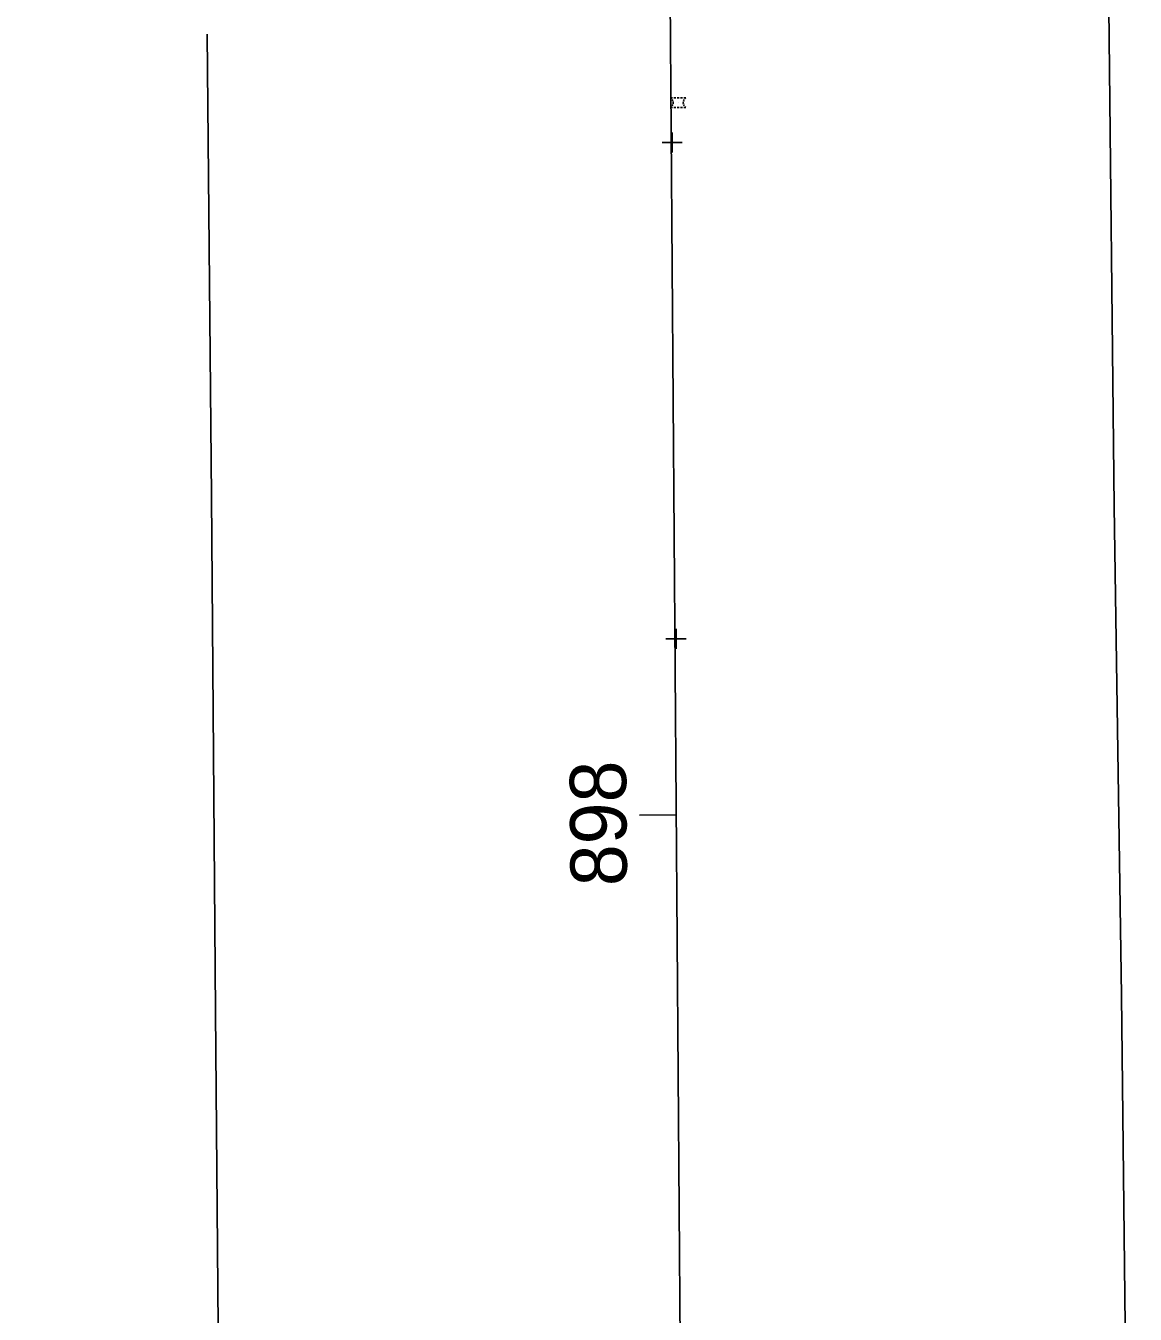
# Model space of a CAD drawing. Extents: x 1546689 to 1550004, y 741079 to 745265.
# Drawn here: x 1548796.6 to 1548851.8, y 745044.7 to 745108.8 of the extents above; entities that cross this region are included whole.
import ezdxf

# ---------------------------------------------------------------- set-up
doc = ezdxf.new("R2010")
doc.units = 0
for name, color, linetype in [('BR_P_Brg_Pad_Hidden', 7, 'Continuous'), ('BR_P_Det_Hidden', 7, 'Continuous'), ('BR_P_Drain_Hidden', 7, 'Continuous'), ('BR_P_Gen_Waterproofing', 7, 'Continuous'), ('BR_P_Slab_Const_Joint', 7, 'Continuous')]:
    doc.layers.add(name, color=color, linetype=linetype)

msp = doc.modelspace()

# ---------------------------------------------------------------- linework, layer by layer
at = {"layer": 'BR_P_Brg_Pad_Hidden'}
msp.add_lwpolyline([(1548851.762, 744992.557), (1548851.612, 745010.399), (1548851.363, 745035.194), (1548851.082, 745060.569), (1548850.709, 745084.888), (1548850.438, 745111.263), (1548850.35, 745126.508)], dxfattribs=at)
at = {"layer": 'BR_P_Det_Hidden'}
for p, q in [((1548827.57, 745248.795), (1548832.816, 744559.562)), ((1548827.109, 745069.54), (1548828.934, 745069.553))]:
    msp.add_line(p, q, dxfattribs=at)
at = {"layer": 'BR_P_Drain_Hidden'}
msp.add_lwpolyline([(1548796.58, 745026.104), (1548800.826, 745026.412), (1548804.475, 745028.932), (1548806.243, 745034.133), (1548806.211, 745036.245), (1548806.019, 745059.777), (1548805.812, 745085.387), (1548805.607, 745108.389)], dxfattribs=at)
at = {"layer": 'BR_P_Gen_Waterproofing'}
for p, q in [((1548828.644, 745105.218), (1548828.744, 745105.218)), ((1548828.812, 745105.218), (1548828.912, 745105.218)), ((1548828.98, 745105.218), (1548829.08, 745105.218)), ((1548829.03, 745104.974), (1548829.03, 745104.974)), ((1548829.147, 745105.218), (1548829.247, 745105.218)), ((1548829.315, 745105.218), (1548829.415, 745105.218)), ((1548828.644, 745104.73), (1548828.744, 745104.73)), ((1548828.812, 745104.73), (1548828.912, 745104.73)), ((1548828.98, 745104.73), (1548829.08, 745104.73)), ((1548829.147, 745104.73), (1548829.247, 745104.73)), ((1548829.315, 745104.73), (1548829.415, 745104.73))]:
    msp.add_line(p, q, dxfattribs=at)
for centre, start, end in [((1548828.492, 745104.974), 42.08468, 58.02616), ((1548828.492, 745104.974), 301.97384, 317.92055), ((1548828.492, 745104.974), 18.88781, 34.82074), ((1548828.492, 745104.974), 325.17819, 341.11108), ((1548828.492, 745104.974), 348.39039, 11.62021), ((1548829.568, 745104.974), 168.38157, 191.60914), ((1548829.568, 745104.974), 145.17819, 161.10978), ((1548829.568, 745104.974), 198.88718, 214.82074), ((1548829.568, 745104.974), 121.97384, 137.91631), ((1548829.568, 745104.974), 222.08173, 238.02616)]:
    msp.add_arc(centre, 0.288, start, end, dxfattribs=at)
at = {"layer": 'BR_P_Slab_Const_Joint'}
for p, q in [((1548828.732, 745103.493), (1548828.732, 745102.493)), ((1548828.232, 745102.993), (1548829.232, 745102.993)), ((1548828.732, 745102.993), (1548828.732, 745102.993)), ((1548828.922, 745078.811), (1548828.922, 745077.811)), ((1548828.422, 745078.311), (1548829.422, 745078.311)), ((1548828.922, 745078.311), (1548828.922, 745078.311))]:
    msp.add_line(p, q, dxfattribs=at)

# ---------------------------------------------------------------- texts
at = {"layer": 'BR_P_Det_Hidden'}
msp.add_text('898', height=2.8, rotation=90.43605, dxfattribs=at).set_placement((1548826.481, 745066.017))

doc.saveas('drawing.dxf')
